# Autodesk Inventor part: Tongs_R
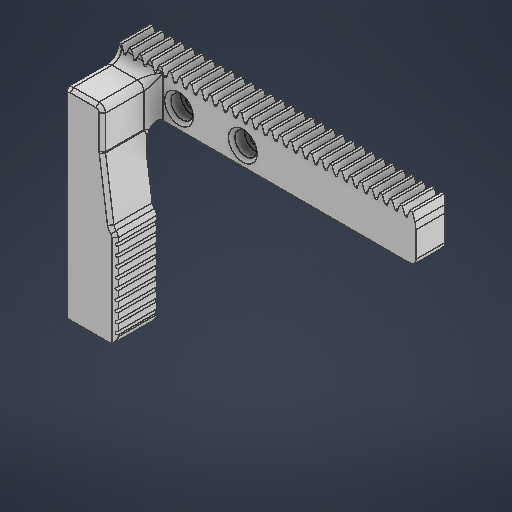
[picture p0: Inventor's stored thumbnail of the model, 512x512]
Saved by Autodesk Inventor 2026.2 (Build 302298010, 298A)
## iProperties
Company: Open CASCADE
Created: 2026-05
Part Number: Tongs_R
Material: 일반
Description: Open CASCADE Model
Document SubType Name: Modeling
Designer: work
Authority: Unknown
Density: 1 g/cm^3
Appearance: 기본값
Sending System: Open CASCADE 7.8
Preprocessor: Open CASCADE STEP processor 7.8
Title: Open CASCADE Shape Model
Author: Author
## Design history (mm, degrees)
feature "기준1"
sketch "스케치1"
  geometry: L1 (0.33, 2)-(1.149, 4.25) reference; L2 (0, 0)-(0.33, 2) reference; L3 (94.248, 0)-(0, 0) reference; L4 (93.917, 2)-(94.248, 0) reference; L5 (93.098, 4.25)-(93.917, 2) reference; L6 (92.256, 4.25)-(93.098, 4.25) reference; L7 (91.437, 2)-(92.256, 4.25) reference; L8 (90.776, 2)-(91.437, 2) reference; L9 (89.957, 4.25)-(90.776, 2) reference; L10 (89.114, 4.25)-(89.957, 4.25) reference; L11 (88.295, 2)-(89.114, 4.25) reference; L12 (87.634, 2)-(88.295, 2) reference; L13 (86.815, 4.25)-(87.634, 2) reference; L14 (85.972, 4.25)-(86.815, 4.25) reference; L15 (85.153, 2)-(85.972, 4.25) reference; L16 (84.493, 2)-(85.153, 2) reference; L17 (83.674, 4.25)-(84.493, 2) reference; L18 (82.831, 4.25)-(83.674, 4.25) reference; L19 (82.012, 2)-(82.831, 4.25) reference; L20 (81.351, 2)-(82.012, 2) reference; L21 (80.532, 4.25)-(81.351, 2) reference; L22 (79.689, 4.25)-(80.532, 4.25) reference; L23 (78.87, 2)-(79.689, 4.25) reference; L24 (78.209, 2)-(78.87, 2) reference; L25 (77.39, 4.25)-(78.209, 2) reference; L26 (76.548, 4.25)-(77.39, 4.25) reference; L27 (75.729, 2)-(76.548, 4.25) reference; L28 (75.068, 2)-(75.729, 2) reference; L29 (74.249, 4.25)-(75.068, 2) reference; L30 (73.406, 4.25)-(74.249, 4.25) reference; L31 (72.587, 2)-(73.406, 4.25) reference; L32 (71.926, 2)-(72.587, 2) reference; L33 (71.107, 4.25)-(71.926, 2) reference; L34 (70.264, 4.25)-(71.107, 4.25) reference; L35 (69.445, 2)-(70.264, 4.25) reference; L36 (68.785, 2)-(69.445, 2) reference; L37 (67.966, 4.25)-(68.785, 2) reference; L38 (67.123, 4.25)-(67.966, 4.25) reference; L39 (66.304, 2)-(67.123, 4.25) reference; L40 (65.643, 2)-(66.304, 2) reference; L41 (64.824, 4.25)-(65.643, 2) reference; L42 (63.981, 4.25)-(64.824, 4.25) reference; L43 (63.162, 2)-(63.981, 4.25) reference; L44 (62.501, 2)-(63.162, 2) reference; L45 (61.682, 4.25)-(62.501, 2) reference; L46 (60.84, 4.25)-(61.682, 4.25) reference; L47 (60.021, 2)-(60.84, 4.25) reference; L48 (59.36, 2)-(60.021, 2) reference; L49 (58.541, 4.25)-(59.36, 2) reference; L50 (57.698, 4.25)-(58.541, 4.25) reference; L51 (56.879, 2)-(57.698, 4.25) reference; L52 (56.218, 2)-(56.879, 2) reference; L53 (55.399, 4.25)-(56.218, 2) reference; L54 (54.556, 4.25)-(55.399, 4.25) reference; L55 (53.738, 2)-(54.556, 4.25) reference; L56 (53.077, 2)-(53.738, 2) reference; L57 (52.258, 4.25)-(53.077, 2) reference; L58 (51.415, 4.25)-(52.258, 4.25) reference; L59 (50.596, 2)-(51.415, 4.25) reference; L60 (49.935, 2)-(50.596, 2) reference; L61 (49.116, 4.25)-(49.935, 2) reference; L62 (48.273, 4.25)-(49.116, 4.25) reference; L63 (47.454, 2)-(48.273, 4.25) reference; L64 (46.793, 2)-(47.454, 2) reference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; 1 further point
  constraints: 8 end point, 2 parallel, 1 horizontal, 1 perpendicular, 1 point on line
  dimensions: "d0" = 10 distance of L123.end L124.end
extrude "돌출1" join sketch "스케치1" stored distance "d1" = 10; taper "d2" = 0 deg
sketch "스케치2"
  geometry: L1 (0.33, 12)-(1.149, 14.25) reference; L2 (0, 10)-(0.33, 12) reference; L3 (0, 10)-(0, 0) reference; L4 (0, 0)-(94.248, 0) reference; L5 (94.248, 0)-(94.248, 10) reference; L6 (93.917, 12)-(94.248, 10) reference; L7 (93.098, 14.25)-(93.917, 12) reference; L8 (92.256, 14.25)-(93.098, 14.25) reference; L9 (91.437, 12)-(92.256, 14.25) reference; L10 (90.776, 12)-(91.437, 12) reference; L11 (89.957, 14.25)-(90.776, 12) reference; L12 (89.114, 14.25)-(89.957, 14.25) reference; L13 (88.295, 12)-(89.114, 14.25) reference; L14 (87.634, 12)-(88.295, 12) reference; L15 (86.815, 14.25)-(87.634, 12) reference; L16 (85.972, 14.25)-(86.815, 14.25) reference; L17 (85.153, 12)-(85.972, 14.25) reference; L18 (84.493, 12)-(85.153, 12) reference; L19 (83.674, 14.25)-(84.493, 12) reference; L20 (82.831, 14.25)-(83.674, 14.25) reference; L21 (82.012, 12)-(82.831, 14.25) reference; L22 (81.351, 12)-(82.012, 12) reference; L23 (80.532, 14.25)-(81.351, 12) reference; L24 (79.689, 14.25)-(80.532, 14.25) reference; L25 (78.87, 12)-(79.689, 14.25) reference; L26 (78.209, 12)-(78.87, 12) reference; L27 (77.39, 14.25)-(78.209, 12) reference; L28 (76.548, 14.25)-(77.39, 14.25) reference; L29 (75.729, 12)-(76.548, 14.25) reference; L30 (75.068, 12)-(75.729, 12) reference; L31 (74.249, 14.25)-(75.068, 12) reference; L32 (73.406, 14.25)-(74.249, 14.25) reference; L33 (72.587, 12)-(73.406, 14.25) reference; L34 (71.926, 12)-(72.587, 12) reference; L35 (71.107, 14.25)-(71.926, 12) reference; L36 (70.264, 14.25)-(71.107, 14.25) reference; L37 (69.445, 12)-(70.264, 14.25) reference; L38 (68.785, 12)-(69.445, 12) reference; L39 (67.966, 14.25)-(68.785, 12) reference; L40 (67.123, 14.25)-(67.966, 14.25) reference; L41 (66.304, 12)-(67.123, 14.25) reference; L42 (65.643, 12)-(66.304, 12) reference; L43 (64.824, 14.25)-(65.643, 12) reference; L44 (63.981, 14.25)-(64.824, 14.25) reference; L45 (63.162, 12)-(63.981, 14.25) reference; L46 (62.501, 12)-(63.162, 12) reference; L47 (61.682, 14.25)-(62.501, 12) reference; L48 (60.84, 14.25)-(61.682, 14.25) reference; L49 (60.021, 12)-(60.84, 14.25) reference; L50 (59.36, 12)-(60.021, 12) reference; L51 (58.541, 14.25)-(59.36, 12) reference; L52 (57.698, 14.25)-(58.541, 14.25) reference; L53 (56.879, 12)-(57.698, 14.25) reference; L54 (56.218, 12)-(56.879, 12) reference; L55 (55.399, 14.25)-(56.218, 12) reference; L56 (54.556, 14.25)-(55.399, 14.25) reference; L57 (53.738, 12)-(54.556, 14.25) reference; L58 (53.077, 12)-(53.738, 12) reference; L59 (52.258, 14.25)-(53.077, 12) reference; L60 (51.415, 14.25)-(52.258, 14.25) reference; L61 (50.596, 12)-(51.415, 14.25) reference; L62 (49.935, 12)-(50.596, 12) reference; L63 (49.116, 14.25)-(49.935, 12) reference; L64 (48.273, 14.25)-(49.116, 14.25) reference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; C1 r 2 at (40, 5.688); C2 r 2 at (20, 5.688); 3 further points
  constraints: 8 end point, 5 point on line, 4 perpendicular, 2 centre point, 2 midpoint, 1 horizontal
  dimensions: "d4" = 0.5625 distance of L126.end point (47.124, 13.688); "d5" = 8 distance of point (47.124, 5.688) point (47.124, 13.688); "d6" = 4 diameter of C1; "d7" = 4 diameter of C2; "d8" = 20 distance of C1.centre C2.centre; "d60" = 20 distance of L128.start C2.centre
extrude "돌출2" cut sketch "스케치2" extent not by distance; stored distance "d10" = 0; taper "d11" = 0 deg
sketch "스케치5"
  geometry: L1 (0, 10)-(12, 10); L2 (12, 10)-(12, -52.624); L3 (12, -52.624)-(0, -52.624); L4 (12, -52.624)-(16, -52.624); L5 (16, -22.624)-(12, -22.624); L6 (12, -22.624)-(12, -52.624); L7 (0, -49.624)-(16, -49.624); C1 r 0.5 at (16, -49.624); C2 r 0.5 at (0, -49.624); C3 r 0.5 at (16, -46.624); C4 r 0.5 at (0, -46.624); C5 r 0.5 at (16, -43.624); C6 r 0.5 at (0, -43.624); C7 r 0.5 at (16, -40.624); C8 r 0.5 at (0, -40.624); C9 r 0.5 at (16, -37.624); C10 r 0.5 at (0, -37.624); C11 r 0.5 at (16, -34.624); C12 r 0.5 at (0, -34.624); C13 r 0.5 at (16, -31.624); C14 r 0.5 at (0, -31.624); C15 r 0.5 at (16, -28.624); C16 r 0.5 at (0, -28.624); C17 r 0.5 at (16, -25.624); C18 r 0.5 at (0, -25.624); 39 further points
  constraints: 18 centre point, 14 end point, 4 horizontal, 3 vertical, 2 parallel, 1 coincident, 1 perpendicular, 40 other
  dimensions: "d36" = 62.624 distance of L1.end L2.end; "d37" = 12 distance of L2.end L3.end; "d38" = 30 distance of L5.start L4.end; "d39" = 4 distance of L2.end L4.end; "d40" = 1 diameter of C1; "d41" = 1 diameter of C2; "d42" = 3 distance between parallel lines of L3 L7; "d45" = 3 distance of L7.end C3.centre
extrude "돌출5" join sketch "스케치5" distance "d50" = 16; taper "d51" = 0 deg
chamfer "모따기2" distance "d52" = 20; stored, may be unused: second distance "d53" = 2, angle "d54" = 171.887 deg
sketch "스케치6"
  geometry: L1 (0, -52.624)-(-16, -52.624) reference; L2 (-3, -52.624)-(-3, -10); L3 (10, 10)-(10, 0) reference; L4 (0, 0)-(10, 0) reference; L5 (0, 0)-(0, -25.124) reference; L6 (0, -25.124)-(-16, -25.124) reference; L7 (-16, 10)-(-16, -25.124) reference; L8 (0, 10)-(-16, 10) reference; L9 (10, 10)-(0, 10) reference; L10 (0, -26.124)-(0, -25.124) reference; L11 (-3, -52.624)-(0, -52.624); L12 (0, -52.624)-(0, -25.124); L13 (0, -25.124)-(-3, -25.124); L14 (-3, -25.124)-(-3, -52.624); A1 r 18.167 centre (15.167, -10) between (0, 0) and (-3, -10); 3 further points
  constraints: 10 end point, 2 parallel, 2 point on circle, 1 centre point, 1 horizontal, 1 perpendicular, 1 point on line, 1 tangent, 1 vertical
  dimensions: "d55" = 10 vertical distance of L4.start L2.end; "d56" = 3 horizontal distance of L4.start L2.end
extrude "돌출6" cut sketch "스케치6" extent not by distance; stored distance "d57" = 0; taper "d58" = 0 deg
fillet "모깎기2" dims "d59" = 3
fillet "모깎기3" dims "d61" = 2
fillet "모깎기4" dims "d62" = 2
chamfer "모따기3" distance "d63" = 1; stored, may be unused: second distance "d64" = 2, angle "d65" = 171.887 deg
sketch "스케치7"
  geometry: L1 (79.248, 2)-(79.248, 10) reference; L2 (78.917, 12)-(79.248, 10) reference; L3 (78.098, 14.25)-(78.917, 12) reference; L4 (77.256, 14.25)-(78.098, 14.25) reference; L5 (76.437, 12)-(77.256, 14.25) reference; L6 (75.776, 12)-(76.437, 12) reference; L7 (74.957, 14.25)-(75.776, 12) reference; L8 (74.114, 14.25)-(74.957, 14.25) reference; L9 (73.295, 12)-(74.114, 14.25) reference; L10 (72.634, 12)-(73.295, 12) reference; L11 (71.815, 14.25)-(72.634, 12) reference; L12 (70.972, 14.25)-(71.815, 14.25) reference; L13 (70.153, 12)-(70.972, 14.25) reference; L14 (69.493, 12)-(70.153, 12) reference; L15 (68.674, 14.25)-(69.493, 12) reference; L16 (67.831, 14.25)-(68.674, 14.25) reference; L17 (67.012, 12)-(67.831, 14.25) reference; L18 (66.351, 12)-(67.012, 12) reference; L19 (65.532, 14.25)-(66.351, 12) reference; L20 (64.689, 14.25)-(65.532, 14.25) reference; L21 (63.87, 12)-(64.689, 14.25) reference; L22 (63.209, 12)-(63.87, 12) reference; L23 (62.39, 14.25)-(63.209, 12) reference; L24 (61.548, 14.25)-(62.39, 14.25) reference; L25 (60.729, 12)-(61.548, 14.25) reference; L26 (60.068, 12)-(60.729, 12) reference; L27 (59.249, 14.25)-(60.068, 12) reference; L28 (58.406, 14.25)-(59.249, 14.25) reference; L29 (57.587, 12)-(58.406, 14.25) reference; L30 (56.926, 12)-(57.587, 12) reference; L31 (56.107, 14.25)-(56.926, 12) reference; L32 (55.264, 14.25)-(56.107, 14.25) reference; L33 (54.445, 12)-(55.264, 14.25) reference; L34 (53.785, 12)-(54.445, 12) reference; L35 (52.966, 14.25)-(53.785, 12) reference; L36 (52.123, 14.25)-(52.966, 14.25) reference; L37 (51.304, 12)-(52.123, 14.25) reference; L38 (50.643, 12)-(51.304, 12) reference; L39 (49.824, 14.25)-(50.643, 12) reference; L40 (48.981, 14.25)-(49.824, 14.25) reference; L41 (48.162, 12)-(48.981, 14.25) reference; L42 (47.501, 12)-(48.162, 12) reference; L43 (46.682, 14.25)-(47.501, 12) reference; L44 (45.84, 14.25)-(46.682, 14.25) reference; L45 (45.021, 12)-(45.84, 14.25) reference; L46 (44.36, 12)-(45.021, 12) reference; L47 (43.541, 14.25)-(44.36, 12) reference; L48 (42.698, 14.25)-(43.541, 14.25) reference; L49 (41.879, 12)-(42.698, 14.25) reference; L50 (41.218, 12)-(41.879, 12) reference; L51 (40.399, 14.25)-(41.218, 12) reference; L52 (39.556, 14.25)-(40.399, 14.25) reference; L53 (38.738, 12)-(39.556, 14.25) reference; L54 (38.077, 12)-(38.738, 12) reference; L55 (37.258, 14.25)-(38.077, 12) reference; L56 (36.415, 14.25)-(37.258, 14.25) reference; L57 (35.596, 12)-(36.415, 14.25) reference; L58 (34.935, 12)-(35.596, 12) reference; L59 (34.116, 14.25)-(34.935, 12) reference; L60 (33.273, 14.25)-(34.116, 14.25) reference; L61 (32.454, 12)-(33.273, 14.25) reference; L62 (31.793, 12)-(32.454, 12) reference; L63 (30.975, 14.25)-(31.793, 12) reference; L64 (30.132, 14.25)-(30.975, 14.25) reference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; C1 r 2 at (25, 5.688) reference; C2 r 2 at (5, 5.688) reference; A1 r 2 centre (77.248, 2) between (77.248, 0) and (79.248, 2) reference; 3 further points
  constraints: 2 coincident
hole "구멍1" sketch "스케치7" at (5, 5.688), (25, 5.688) diameter "d66" = 4; stored, may be unused: countersink angle "d70" = 90 deg, drill point angle "d72" = 118 deg; dims "d67" = 6, "d68" = 7, "d69" = 4, "d71" = 3 (= d59)
chamfer "모따기4" distance "d73" = 1; stored, may be unused: second distance "d74" = 2, angle "d75" = 171.887 deg
node "솔리드1"
node "투영된 루프1"
node "투영된 루프2"
node "스케치 - 직사각형 패턴2" dims "d45" = 3, "d48" = 10
node "투영된 루프5"
node "투영된 루프6"
feature "A9D066F2-1C7D-4E18-AEED-F7BC21143FA4" dims "d66" = 4, "d67" = 6, "d68" = 7, "d69" = 4, "d70" = 90 deg, "d71" = 3 (= d59), "d72" = 118 deg
